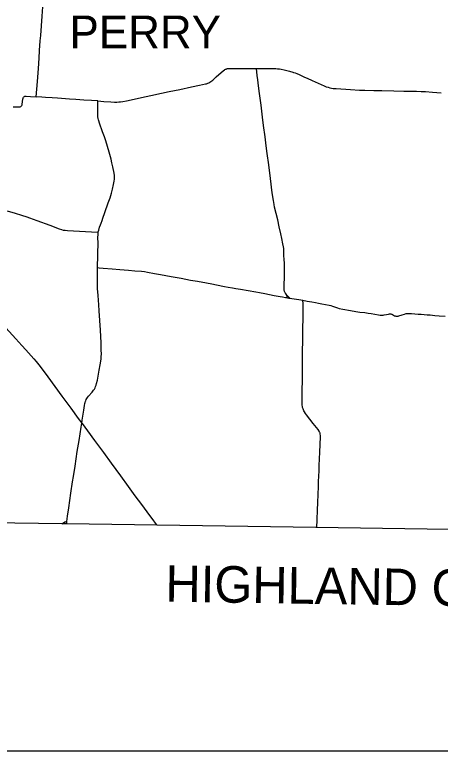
# Model space of a CAD drawing. Extents: x 1597222 to 1925846, y 496284 to 911751.
# Drawn here: x 1703147 to 1714792, y 496867 to 517019 of the extents above; entities that cross this region are included whole.
import ezdxf

# ---------------------------------------------------------------- set-up
doc = ezdxf.new("R2010")
doc.units = 0
for name, color, linetype in [('GM_X_Adjacent_County_Text', 7, 'Continuous'), ('GM_X_County', 7, 'Continuous'), ('GM_X_County_Road', 7, 'Continuous'), ('GM_X_Township', 7, 'Continuous'), ('GM_X_Township_Road', 7, 'Continuous'), ('GM_X_Township_Text', 7, 'Continuous'), ('SC_Scratch1', 7, 'Continuous')]:
    doc.layers.add(name, color=color, linetype=linetype)

msp = doc.modelspace()

# ---------------------------------------------------------------- linework, layer by layer
at = {"layer": 'GM_X_County'}
msp.add_lwpolyline([(1729526, 515601), (1727396, 512075), (1725220, 508449), (1721935, 502985), (1721844, 502834), (1721165, 502848), (1719280, 502875), (1716307, 502917), (1714432, 502944), (1711386, 502989), (1707043, 503052), (1704566, 503090), (1704437, 503092), (1698641, 503176), (1693676, 503248), (1687539, 503338), (1685835, 503363), (1685430, 503373), (1682405, 503448), (1678903, 503534), (1673166, 503675)], dxfattribs=at)
at = {"layer": 'GM_X_County_Road'}
for points in [[(1703737, 514771), (1703769, 515191), (1703794, 515551), (1703815, 515829), (1703829, 516042), (1703846, 516304), (1703858, 516452), (1703896, 516976), (1703915, 517238)], [(1705423, 514660), (1705249, 514672), (1705036, 514685), (1704823, 514699), (1704643, 514711), (1704316, 514733), (1704168, 514742), (1703988, 514753), (1703890, 514761), (1703737, 514771)], [(1705433, 511065), (1705435, 511077), (1705446, 511125), (1705469, 511204), (1705491, 511266), (1705509, 511312), (1705537, 511389), (1705561, 511450), (1705615, 511605), (1705708, 511868), (1705757, 512007), (1705777, 512070), (1705794, 512133), (1705820, 512245), (1705848, 512373), (1705867, 512469), (1705874, 512518), (1705876, 512551), (1705876, 512584), (1705874, 512616), (1705864, 512681), (1705830, 512859), (1705806, 512971), (1705782, 513066), (1705731, 513257), (1705687, 513415), (1705640, 513572), (1705603, 513681), (1705553, 513819), (1705467, 514050), (1705446, 514112), (1705438, 514144), (1705431, 514176), (1705424, 514225), (1705422, 514274), (1705421, 514372), (1705423, 514503), (1705423, 514602), (1705423, 514660)], [(1705416, 510101), (1705421, 510438), (1705426, 510815), (1705425, 510881), (1705425, 510930), (1705427, 510996), (1705433, 511061), (1705433, 511065)], [(1704982, 505846), (1704995, 505925), (1705040, 506200), (1705061, 506330), (1705070, 506378), (1705077, 506410), (1705087, 506442), (1705092, 506457), (1705105, 506487), (1705121, 506515), (1705140, 506543), (1705169, 506582), (1705266, 506695), (1705307, 506747), (1705326, 506773), (1705345, 506809), (1705362, 506844), (1705376, 506880), (1705389, 506928), (1705409, 507023), (1705462, 507296), (1705489, 507441), (1705504, 507538), (1705512, 507604), (1705516, 507669), (1705519, 507734), (1705517, 507850), (1705511, 508044), (1705491, 508390), (1705461, 508914), (1705449, 509078), (1705427, 509339), (1705419, 509437), (1705416, 509519), (1705414, 509650), (1705416, 510093), (1705416, 510101)], [(1702811, 508555), (1703173, 508153), (1703338, 507970), (1703448, 507848), (1703668, 507605), (1703732, 507531), (1703805, 507441), (1703895, 507324), (1704051, 507113), (1704438, 506584), (1704682, 506254), (1704886, 505976), (1704982, 505846)], [(1704574, 503156), (1704593, 503298), (1704624, 503525), (1704684, 503931), (1704730, 504239), (1704753, 504385), (1704798, 504664), (1704860, 505066), (1704911, 505374), (1704963, 505731), (1704982, 505846)], [(1704982, 505846), (1704993, 505831), (1705139, 505633), (1705332, 505367), (1705439, 505223), (1705576, 505038), (1705789, 504747), (1706042, 504403), (1706255, 504112), (1706438, 503860), (1706526, 503741), (1706642, 503582), (1706808, 503358), (1706925, 503200), (1706994, 503108), (1707035, 503054)], [(1704565, 503090), (1704569, 503119), (1704574, 503156)]]:
    msp.add_lwpolyline(points, dxfattribs=at)
at = {"layer": 'GM_X_Township'}
msp.add_lwpolyline([(1716307, 502917), (1714432, 502944), (1711386, 502989), (1707043, 503052), (1704566, 503090), (1704437, 503092), (1698641, 503176)], dxfattribs=at)
at = {"layer": 'GM_X_Township_Road'}
for points in [[(1705423, 514660), (1705583, 514649), (1705780, 514635), (1705878, 514631), (1705943, 514631), (1705992, 514633), (1706041, 514638), (1706105, 514648), (1706202, 514667), (1706330, 514694), (1706619, 514755), (1706875, 514810), (1707164, 514872), (1707373, 514916), (1707662, 514976), (1707982, 515044), (1708207, 515092), (1708368, 515125), (1708399, 515132), (1708430, 515142), (1708460, 515155), (1708487, 515171), (1708514, 515190), (1708564, 515232), (1708663, 515318), (1708797, 515438), (1708847, 515481), (1708887, 515511), (1708901, 515520), (1708916, 515527), (1708931, 515534), (1708947, 515540), (1708963, 515544), (1708980, 515547), (1709013, 515551), (1709062, 515552), (1709226, 515550), (1709686, 515549), (1709760, 515549)], [(1709760, 515549), (1709882, 515549), (1710063, 515548), (1710194, 515548), (1710293, 515546), (1710342, 515543), (1710391, 515538), (1710439, 515529), (1710520, 515510), (1710662, 515472), (1710757, 515446), (1710772, 515441)], [(1710608, 509327), (1710603, 509332), (1710572, 509370), (1710553, 509397), (1710544, 509412), (1710537, 509427), (1710531, 509442), (1710526, 509459), (1710523, 509475), (1710521, 509508), (1710522, 509607), (1710523, 509689), (1710526, 509771), (1710527, 509967), (1710528, 510066), (1710528, 510148), (1710526, 510213), (1710520, 510328), (1710514, 510426), (1710512, 510492), (1710510, 510573), (1710507, 510622), (1710501, 510671), (1710487, 510751), (1710457, 510896), (1710429, 511024), (1710387, 511216), (1710343, 511408), (1710299, 511583), (1710255, 511758), (1710242, 511823), (1710224, 511937), (1710196, 512148), (1710146, 512539), (1710097, 512913), (1710058, 513222), (1710031, 513434), (1709999, 513678), (1709957, 513987), (1709929, 514215), (1709907, 514378), (1709887, 514540), (1709871, 514671), (1709846, 514866), (1709820, 515078), (1709800, 515241), (1709785, 515354), (1709760, 515549)], [(1710772, 515441), (1710820, 515426), (1710866, 515409), (1710927, 515383), (1711075, 515315), (1711150, 515282), (1711284, 515221), (1711614, 515074), (1711674, 515049), (1711721, 515033), (1711768, 515020), (1711815, 515010), (1711864, 515003), (1711945, 514997), (1712338, 514973), (1712584, 514958), (1712731, 514952), (1712977, 514946), (1713190, 514942), (1713518, 514935), (1713797, 514929), (1713961, 514927), (1714141, 514925), (1714272, 514920), (1714387, 514914), (1714583, 514899), (1714812, 514884)], [(1703104, 514500), (1703235, 514497), (1703267, 514497), (1703283, 514498), (1703299, 514500), (1703313, 514505), (1703326, 514513), (1703336, 514523), (1703343, 514537), (1703349, 514551), (1703352, 514567), (1703372, 514714), (1703375, 514730), (1703379, 514746), (1703386, 514762), (1703397, 514776), (1703411, 514786), (1703427, 514792), (1703445, 514794), (1703462, 514794), (1703576, 514782), (1703737, 514771)], [(1702944, 511657), (1703163, 511589), (1703335, 511535), (1703475, 511491), (1703553, 511464), (1703753, 511391), (1704106, 511259), (1704366, 511161), (1704428, 511140), (1704476, 511128), (1704524, 511120), (1704590, 511113), (1705080, 511084), (1705408, 511066), (1705433, 511065)], [(1705416, 510101), (1705455, 510097), (1705569, 510088), (1705815, 510067), (1706027, 510049), (1706256, 510030), (1706436, 510015), (1706616, 510000), (1706698, 509990), (1706779, 509978), (1706972, 509942), (1707134, 509913), (1707424, 509859), (1707699, 509809), (1707957, 509760), (1708150, 509725), (1708392, 509680), (1708537, 509653), (1708666, 509627), (1708892, 509584), (1708989, 509566), (1709102, 509547), (1709199, 509531), (1709328, 509509), (1709538, 509470), (1709748, 509433), (1709845, 509415), (1709990, 509389), (1710119, 509364), (1710248, 509341), (1710409, 509312), (1710474, 509300), (1710554, 509285), (1710579, 509281)], [(1710579, 509281), (1710589, 509297), (1710602, 509318), (1710608, 509327)], [(1710579, 509281), (1710651, 509268), (1710677, 509264)], [(1710677, 509264), (1710651, 509286), (1710626, 509308), (1710608, 509327)], [(1710677, 509264), (1710732, 509255), (1710926, 509223), (1711033, 509205)], [(1711413, 502991), (1711419, 503196), (1711433, 503477), (1711442, 503665), (1711450, 503897), (1711456, 504100), (1711461, 504245), (1711467, 504392), (1711474, 504536), (1711479, 504687), (1711486, 504868), (1711493, 505048), (1711511, 505474), (1711511, 505507), (1711508, 505539), (1711502, 505570), (1711497, 505585), (1711491, 505600), (1711475, 505628), (1711447, 505668), (1711317, 505837), (1711134, 506069), (1711105, 506109), (1711078, 506150), (1711062, 506179), (1711048, 506209), (1711036, 506240), (1711026, 506272), (1711020, 506304), (1711015, 506337), (1711012, 506387), (1711013, 506469), (1711016, 506600), (1711016, 506682), (1711017, 506813), (1711019, 506945), (1711021, 507125), (1711022, 507256), (1711023, 507371), (1711025, 507551), (1711026, 507764), (1711030, 508142), (1711033, 508421), (1711035, 508519), (1711036, 508633), (1711036, 508732), (1711037, 508814), (1711038, 508896), (1711040, 508978), (1711039, 509059), (1711036, 509141), (1711034, 509173), (1711033, 509205)], [(1711033, 509205), (1711152, 509185), (1711281, 509161), (1711378, 509142), (1711458, 509126), (1711555, 509108), (1711652, 509093), (1711749, 509075), (1711796, 509063), (1711843, 509049), (1711951, 509008), (1711982, 508998), (1712029, 508984), (1712125, 508964), (1712335, 508925), (1712481, 508900), (1712594, 508884), (1712725, 508870), (1712823, 508858), (1712904, 508847), (1713098, 508811), (1713146, 508803), (1713179, 508800), (1713212, 508800), (1713228, 508802), (1713260, 508807), (1713325, 508820), (1713373, 508830), (1713406, 508833), (1713422, 508832), (1713438, 508831), (1713454, 508827), (1713470, 508822), (1713485, 508815), (1713514, 508800), (1713543, 508784), (1713558, 508778), (1713574, 508774), (1713590, 508771), (1713606, 508771), (1713622, 508772), (1713638, 508776), (1713654, 508780), (1713747, 508812), (1713811, 508830), (1713859, 508840), (1713891, 508845), (1713924, 508847), (1713957, 508847), (1714006, 508844), (1714186, 508830), (1714267, 508823), (1714431, 508810), (1714513, 508804), (1714578, 508799), (1714643, 508794), (1714758, 508785), (1714922, 508773)], [(1704436, 503092), (1704478, 503119), (1704517, 503142), (1704533, 503148), (1704552, 503153), (1704574, 503156)]]:
    msp.add_lwpolyline(points, dxfattribs=at)
at = {"layer": 'SC_Scratch1'}
msp.add_lwpolyline([(1597222, 631367), (1793472, 631367), (1793472, 496867), (1597222, 496867)], close=True, dxfattribs=at)

# ---------------------------------------------------------------- texts
at = {"layer": 'GM_X_Adjacent_County_Text'}
msp.add_text('HIGHLAND COUNTY', height=1000, rotation=359.149, dxfattribs=at).set_placement((1707265, 500959))
at = {"layer": 'GM_X_Township_Text'}
msp.add_text('PERRY', height=900, rotation=0, dxfattribs=at).set_placement((1704646, 516097))

doc.saveas('drawing.dxf')
